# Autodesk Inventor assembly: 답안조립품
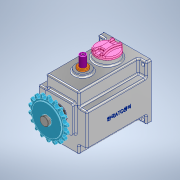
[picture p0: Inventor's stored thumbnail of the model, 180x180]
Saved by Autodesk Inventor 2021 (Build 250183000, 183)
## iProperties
Created: 2022-08
Part Number: 답안조립품
Document SubType Name: Assembly
Designer: Owner
Author: Owner
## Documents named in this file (16)
- C:\Users\Owner\Desktop\720810V1002\답안조립품.iam
- C:\Users\Owner\Desktop\720810V1002\본체.ipt
- C:\Users\Owner\Desktop\720810V1002\멈춤나사 M3.ipt
- C:\Users\Owner\Desktop\720810V1002\메인 축.ipt
- C:\Users\Owner\Desktop\720810V1002\베어링 608.ipt
- C:\Users\Owner\Desktop\720810V1002\베어링 6003.ipt
- C:\Users\Owner\Desktop\720810V1002\볼트 M4 x 10.ipt
- C:\Users\Owner\Desktop\720810V1002\부시.ipt
- C:\Users\Owner\Desktop\720810V1002\상부 캡.ipt
- C:\Users\Owner\Desktop\720810V1002\서브 축.ipt
- C:\Users\Owner\Desktop\720810V1002\스프로킷.ipt
- C:\Users\Owner\Desktop\720810V1002\슬라이더.ipt
- C:\Users\Owner\Desktop\720810V1002\오일 실 8 x 22 x 7.ipt
- C:\Users\Owner\Desktop\720810V1002\오일 실 17 x 32 x 8.ipt
- C:\Users\Owner\Desktop\720810V1002\커버.ipt
- C:\Users\Owner\Desktop\720810V1002\키 5 x 5.ipt
